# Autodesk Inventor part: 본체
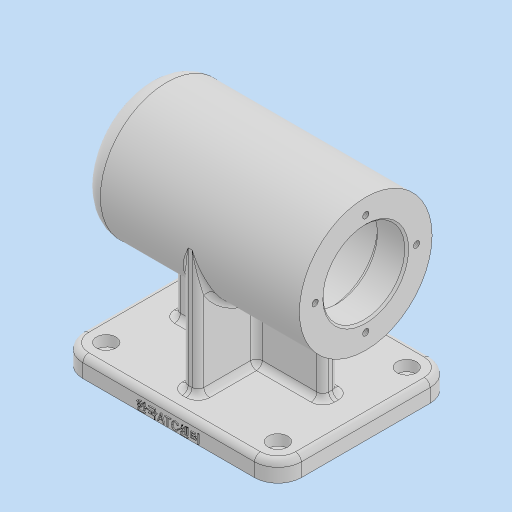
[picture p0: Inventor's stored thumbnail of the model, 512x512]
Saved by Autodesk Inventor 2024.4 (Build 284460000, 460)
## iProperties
Created: 2026-08
Part Number: 본체
Material: 일반
Document SubType Name: Modeling
Designer: home
Density: 1 g/cm^3
Appearance: 기본값
Mass: 379.712 g
Surface Area: 758.395 cm^2
Volume: 379.712 cm^3
Author: home
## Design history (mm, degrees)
sketch "스케치1"
  geometry: L1 (-56, 0)-(56, 0); L2 (-56, 0)-(-56, 34); L3 (-56, 34)-(56, 34); L4 (56, 34)-(56, 0); L5 (56, 21)-(41, 21); L6 (41, 21)-(41, 24); L7 (41, 24)-(-13, 24); L8 (-13, 24)-(-13, 21); L9 (-13, 21)-(-25, 21); L10 (-25, 21)-(-25, 17.5); L11 (-25, 17.5)-(-43, 17.5); L12 (-43, 17.5)-(-43, 16); L13 (-43, 16)-(-47, 16); L14 (-47, 16)-(-47, 10.5); L15 (-47, 10.5)-(-50, 10.5); L16 (-50, 10.5)-(-50, 0); 2 further points
  constraints: 32 end point, 12 perpendicular, 3 horizontal, 2 point on line, 1 coincident, 1 midpoint, 1 vertical
  dimensions: "d0" = 112 distance of L1.start L1.end; "d1" = 68 diameter of L3 L1; "d2" = 42 diameter of L5 L1; "d3" = 48 diameter of L7 L1; "d4" = 42 diameter of L9 L1; "d5" = 35 diameter of L11 L1; "d6" = 32 diameter of L13 L1; "d7" = 21 diameter of L15 L1; "d8" = 3 distance between parallel lines of L14 L16; "d9" = 103 distance between parallel lines of L4 L14; "d10" = 18 distance between parallel lines of L12 L10; "d11" = 81 distance between parallel lines of L4 L10; "d12" = 54 distance between parallel lines of L6 L8; "d13" = 15 distance between parallel lines of L4 L6
revolve "회전1" sketch "스케치1" stored, may be unused: angle "d14" = 90 deg
fillet "모깎기1" dims "d15" = 3
fillet "모깎기2" dims "d16" = 0.6
chamfer "모따기1" distance "d17" = 1; stored, may be unused: second distance "d18" = 2, angle "d19" = 45 deg
fillet "모깎기3" dims "d20" = 10
sketch "스케치2" dims "d21" = 52
  geometry: C1 r 34 at (0, 0) reference; 3 further points
  constraints: 2 vertical alignment, 3 other
hole "구멍1" sketch "스케치2" at (0, 26) diameter "d22" = 3.242; stored, may be unused: countersink angle "d26" = 90 deg, drill point angle "d28" = 118 deg; dims "d23" = 8, "d24" = 4, "d25" = 2, "d27" = 10
node "작업 평면1"
sketch "스케치3"
  geometry: L1 (56, -45)-(-56, -45); L2 (-56, -45)-(-56, 45); L3 (-56, 45)-(56, 45); L4 (56, 45)-(56, -45); 3 further points
  constraints: 8 end point, 2 midpoint, 2 parallel, 1 horizontal, 1 horizontal alignment, 1 perpendicular, 1 vertical alignment
  dimensions: "d33" = 112 distance of L2.end L3.end; "d34" = 90 distance of L1.end L2.end
extrude "돌출1" join sketch "스케치3" distance "d35" = 10; taper "d36" = 0 deg
sketch "스케치4"
  geometry: L1 (-4, 34)-(4, 34); L2 (4, 34)-(4, -34); L3 (4, -34)-(-4, -34); L4 (-4, -34)-(-4, 34); L5 (-38, 4)-(38, 4); L6 (38, 4)-(38, -4); L7 (38, -4)-(-38, -4); L8 (-38, -4)-(-38, 4); 9 further points
  constraints: 16 end point, 4 midpoint, 4 parallel, 2 horizontal, 2 horizontal alignment, 2 perpendicular, 2 vertical alignment
  dimensions: "d37" = 8 distance of L2.end L3.end; "d38" = 68 distance of L1.end L2.end; "d39" = 76 distance of L6.end L7.end; "d40" = 8 distance of L5.end L6.end
extrude "돌출2" join sketch "스케치4" stored distance "d41" = 10; taper "d42" = 0 deg
fillet "모깎기4" dims "d43" = 12
sketch "스케치5"
  geometry: A1 r 12 centre (44, -33) between (44, -45) and (56, -33) reference; A2 r 12 centre (-44, -33) between (-56, -33) and (-44, -45) reference; A3 r 12 centre (44, 33) between (56, 33) and (44, 45) reference; A4 r 12 centre (-44, 33) between (-44, 45) and (-56, 33) reference; 5 further points
  constraints: 4 coincident
hole "구멍2" sketch "스케치5" at (44, -33), (-44, -33), (44, 33), (-44, 33) diameter "d44" = 5.5; stored, may be unused: countersink angle "d48" = 90 deg, drill point angle "d50" = 118 deg; dims "d45" = 8, "d46" = 10, "d47" = 5.5, "d49" = 11.8
fillet "모깎기5" dims "d51" = 3
fillet "모깎기6" dims "d52" = 3
fillet "모깎기7" dims "d53" = 3
sketch "스케치6"
  geometry: L1 (0, 0)-(88, 0) reference; 2 further points
  constraints: 1 vertical alignment, 1 other
  dimensions: "d54" = 3 distance from line of L1 point (44, 3)
feature "엠보싱1" sketch "스케치6" dims "d0" = 112, "d1" = 68, "d2" = 42, "d3" = 48, "d4" = 42, "d5" = 35, "d6" = 32, "d7" = 21, "d8" = 3, "d9" = 103, "d10" = 18, "d11" = 81, "d12" = 54, "d13" = 15, "d55" = 0.5, "d56" = 0
feature "ʕ耀ʗ耀ʙ耀ʛ耀ʝ耀ʟ耀ʡ耀ʣ耀" dims "d0" = 112, "d1" = 68, "d2" = 42, "d3" = 48, "d4" = 42, "d5" = 35, "d6" = 32, "d7" = 21, "d8" = 3, "d9" = 103, "d10" = 18, "d11" = 81, "d12" = 54, "d13" = 15, "d14" = 90 deg, "d15" = 3, "d16" = 0.6, "d17" = 1, "d18" = 2, "d19" = 45 deg, "d20" = 10, "d21" = 52, "d22" = 3.242, "d23" = 8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
node "솔리드1"
pattern_circular "원형 패턴1" dims angle "d30" = 360 deg
feature "A9D066F2-1C7D-4E18-AEED-F7BC21143FA4" dims "d44" = 5.5, "d45" = 8, "d46" = 10, "d47" = 5.5, "d48" = 90 deg, "d49" = 11.8, "d50" = 118 deg
